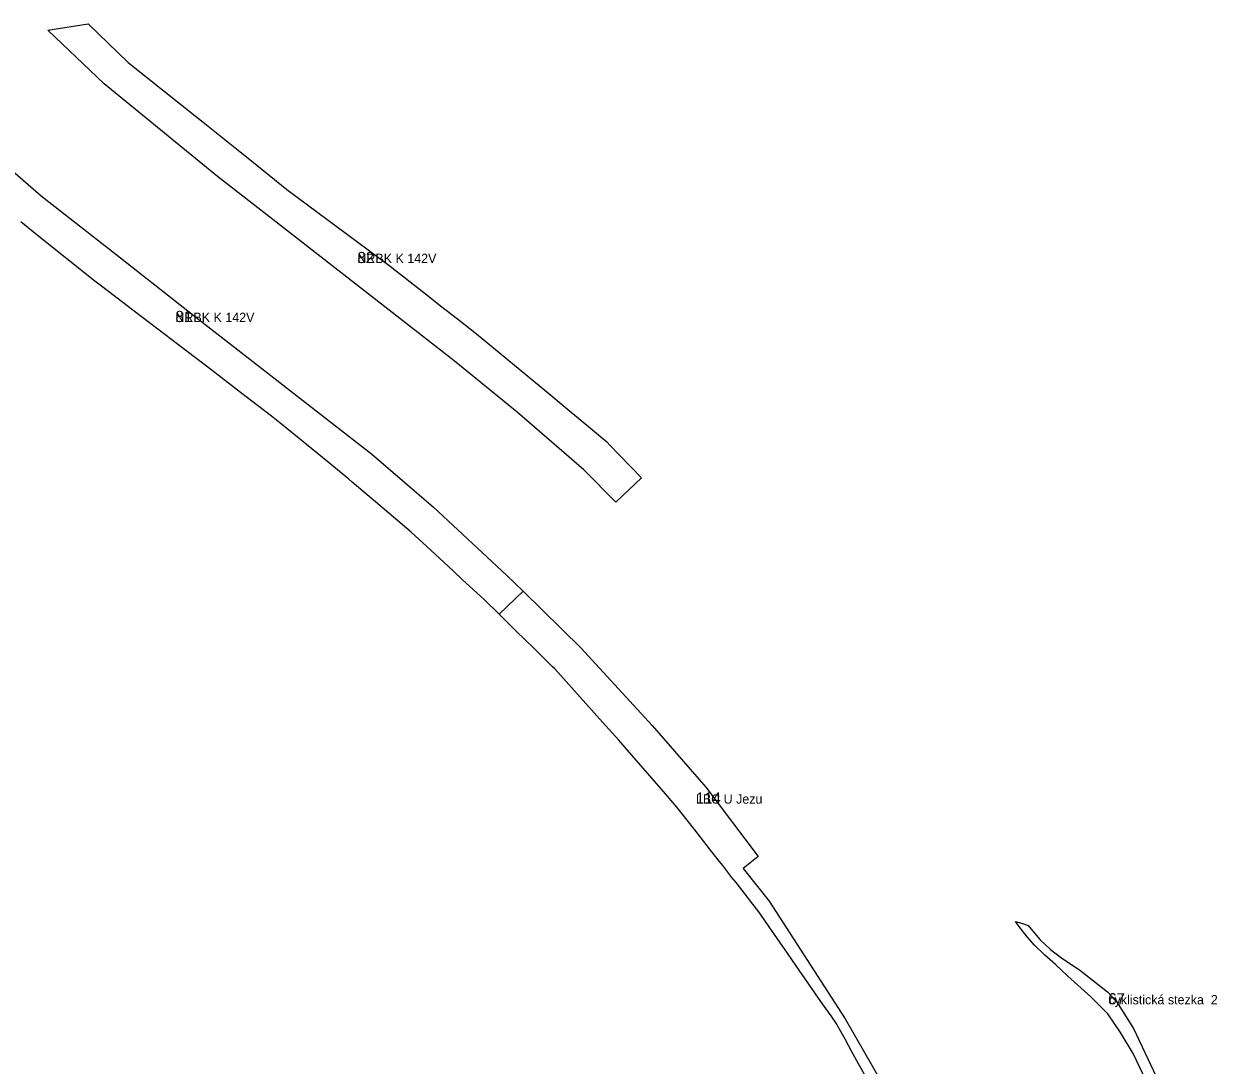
# Model space of a CAD drawing. Extents: x -535270 to -532834, y -1165802 to -1163869.
# Drawn here: x -533624 to -532984, y -1164800 to -1164241 of the extents above; entities that cross this region are included whole.
import ezdxf

# ---------------------------------------------------------------- set-up
doc = ezdxf.new("R2010")
doc.units = 0
for name, color, linetype in [('96120023', 7, 'Continuous'), ('96140023', 7, 'Continuous'), ('ID_VPO', 7, 'Continuous'), ('ID_VPS', 7, 'Continuous')]:
    doc.layers.add(name, color=color, linetype=linetype)

msp = doc.modelspace()

# ---------------------------------------------------------------- linework, layer by layer
at = {"layer": '96120023'}
msp.add_lwpolyline([(-533076.18, -1164740.57), (-533081.8, -1164735.24), (-533085.76, -1164730.68), (-533090.16, -1164724.94), (-533091.95, -1164722.47), (-533088.71, -1164723.46), (-533085.24, -1164724.57), (-533082.73, -1164727.77), (-533078.8, -1164732.29), (-533073.19, -1164737.59), (-533067.06, -1164742.2), (-533059.29, -1164747.31), (-533057.72, -1164748.34), (-533042.69, -1164760.29), (-533037.82, -1164765.42), (-533028.64, -1164779.86), (-533014.98, -1164809.1), (-533020.22, -1164811.44), (-533028.94, -1164793.37), (-533035.71, -1164782.12), (-533042.43, -1164772.05), (-533051.59, -1164762.94), (-533063.86, -1164751.81), (-533070.52, -1164745.61)], close=True, dxfattribs=at)
at = {"layer": '96140023'}
msp.add_lwpolyline([(-533567.95, -1164261.82), (-533530.25, -1164291.87), (-533527.78, -1164293.84), (-533508.97, -1164308.83), (-533498.95, -1164316.9), (-533482.76, -1164329.92), (-533428.16, -1164370.44), (-533407.7, -1164386.45), (-533400.38, -1164392.18), (-533391.36, -1164399.24), (-533381.09, -1164407.28), (-533371.94, -1164414.84), (-533357.65, -1164426.65), (-533352.45, -1164430.94), (-533347.48, -1164435.05), (-533344.43, -1164437.59), (-533332.48, -1164447.55), (-533320, -1164457.95), (-533311.26, -1164465.24), (-533309.57, -1164466.99), (-533304.36, -1164472.39), (-533292.65, -1164484.53), (-533306.34, -1164497.64), (-533323.6, -1164480.19), (-533359.31, -1164449.39), (-533393.01, -1164421.73), (-533493.52, -1164343.51), (-533520.08, -1164322.87), (-533580.88, -1164273.2), (-533611.13, -1164244.35), (-533589.48, -1164241.03)], close=True, dxfattribs=at)
for points in [[(-533637.12, -1164313.74), (-533614.65, -1164333.34), (-533574.57, -1164364.55), (-533529.97, -1164399.56), (-533437.52, -1164471.63), (-533404.17, -1164500.26), (-533365.03, -1164536.67), (-533356.16, -1164545.37), (-533369.01, -1164557.68), (-533376.87, -1164549.96), (-533378.75, -1164548.22), (-533388.71, -1164539.01), (-533393.52, -1164534.57), (-533398.68, -1164529.8), (-533407.83, -1164521.35), (-533416.13, -1164513.68), (-533419.75, -1164510.6), (-533433.01, -1164499.36), (-533447.72, -1164486.86), (-533449.65, -1164485.24), (-533463.74, -1164473.66), (-533485.66, -1164455.66), (-533489.36, -1164452.83), (-533491.1, -1164451.5), (-533507.65, -1164438.78), (-533522.97, -1164427.03), (-533540.77, -1164413.38), (-533548.26, -1164407.66), (-533564.8, -1164395.06), (-533582.28, -1164381.75), (-533585.87, -1164379.01), (-533616.81, -1164354.28), (-533625.55, -1164347.3)], [(-533172.45, -1164805.52), (-533176.14, -1164798.83), (-533179.93, -1164791.97), (-533183.43, -1164785.63), (-533187.14, -1164778.93), (-533187.91, -1164777.51), (-533190.93, -1164773.16), (-533195.08, -1164767.19), (-533199.21, -1164761.24), (-533203.5, -1164755.07), (-533207.59, -1164749.17), (-533212, -1164742.81), (-533214.36, -1164739.41), (-533218.37, -1164733.63), (-533224.16, -1164725.28), (-533228.43, -1164719.12), (-533230.18, -1164716.6), (-533232.82, -1164713.23), (-533237.07, -1164707.79), (-533241.91, -1164701.61), (-533244.07, -1164698.85), (-533249.02, -1164692.52), (-533250.95, -1164690.07), (-533256.12, -1164683.46), (-533263.96, -1164673.42), (-533271.44, -1164663.87), (-533272.67, -1164662.3), (-533275.61, -1164658.9), (-533279.79, -1164654.05), (-533288.14, -1164644.37), (-533296.52, -1164634.66), (-533301.29, -1164629.13), (-533304.78, -1164625.25), (-533313.54, -1164615.51), (-533322.44, -1164605.61), (-533339.13, -1164587.05), (-533340.54, -1164585.66), (-533350.43, -1164575.94), (-533359.97, -1164566.56), (-533369.01, -1164557.68), (-533356.16, -1164545.37), (-533325.21, -1164575.74), (-533286.88, -1164617.4), (-533258.18, -1164650.51), (-533230.07, -1164687.65), (-533238.09, -1164694.07), (-533224.07, -1164711.63), (-533183.34, -1164774.65), (-533157.83, -1164819.27)]]:
    msp.add_lwpolyline(points, dxfattribs=at)

# ---------------------------------------------------------------- texts
at = {"layer": '96120023'}
msp.add_text('cyklistická stezka  2', height=5, rotation=360, dxfattribs=at).set_placement((-533042.2, -1164766.95))
at = {"layer": '96140023'}
for s, rotation, p in [('NRBK K 142V', 360, (-533444.99, -1164369.34)), ('NRBK K 142V', 0, (-533542.6, -1164400.97)), ('LBC U Jezu', 360, (-533263.42, -1164659.29))]:
    msp.add_text(s, height=5, rotation=rotation, dxfattribs=at).set_placement(p)
at = {"layer": 'ID_VPO'}
for s, rotation, p in [('82', 360, (-533444.99, -1164369.34)), ('81', 0, (-533542.6, -1164400.97)), ('114', 0, (-533263.42, -1164659.29))]:
    msp.add_text(s, height=6, rotation=rotation, dxfattribs=at).set_placement(p)
at = {"layer": 'ID_VPS'}
msp.add_text('67', height=6, rotation=360, dxfattribs=at).set_placement((-533042.2, -1164766.95))

doc.saveas('drawing.dxf')
